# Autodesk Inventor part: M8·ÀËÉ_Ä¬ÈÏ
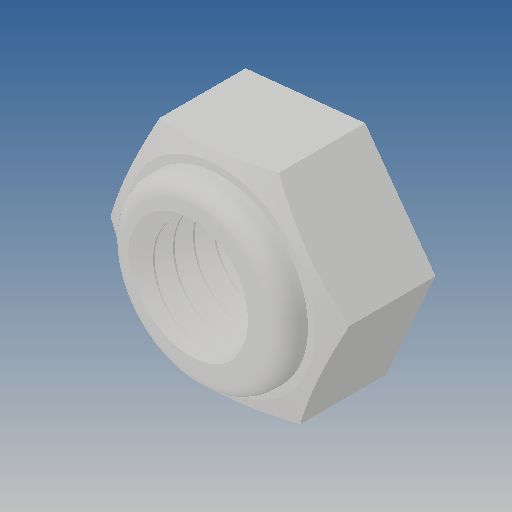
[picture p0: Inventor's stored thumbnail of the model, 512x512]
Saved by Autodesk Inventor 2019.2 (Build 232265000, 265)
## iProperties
Created: 2010-06
Part Number: M8·ÀËÉ_Ä¬ÈÏ
Material: Ogólny
Document SubType Name: Modeling
Designer: CADENGINEERING4
Density: 1 g/cm^3
Appearance: Domyślna
Author: CADENGINEERING4
Revision Number: ÈÎºÎ
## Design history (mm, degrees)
feature "NONE"
node "Bryła1"
